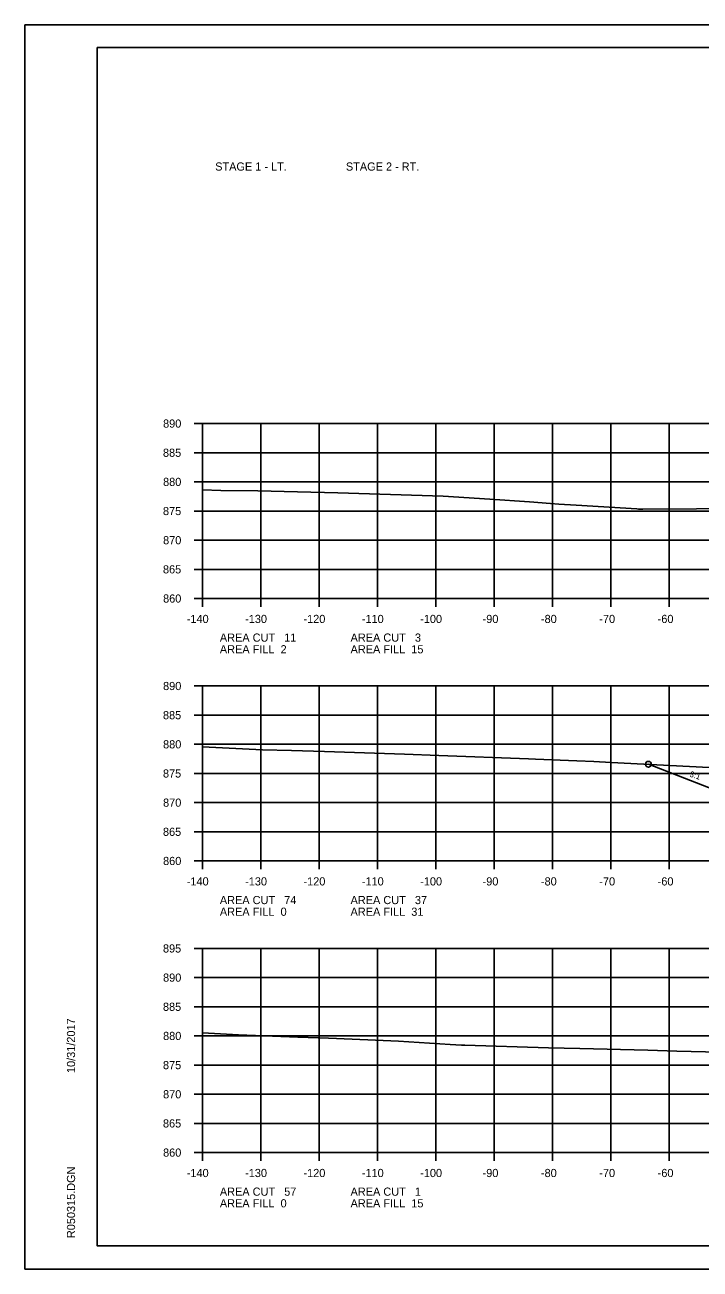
# Model space of a CAD drawing. Extents: x 1486524 to 1499135, y 326561 to 337924.
# Drawn here: x 1488812.5 to 1488928.2, y 332566 to 332779.3 of the extents above; entities that cross this region are included whole.
import ezdxf

# ---------------------------------------------------------------- set-up
doc = ezdxf.new("R2010")
doc.units = 0
for name, color, linetype in [('Default', 7, 'Continuous'), ('E_Const Align', 7, 'Continuous'), ('E_Const Align Station', 7, 'Continuous'), ('E_Ownership Information', 7, 'Continuous'), ('E_Property Line', 7, 'Continuous'), ('E_Quarter Calls', 7, 'Continuous'), ('E_Title Sheet', 7, 'Continuous'), ('E_Tract Number', 7, 'Continuous'), ('R_Xsect Slope', 7, 'Continuous')]:
    doc.layers.add(name, color=color, linetype=linetype)

msp = doc.modelspace()

# ---------------------------------------------------------------- linework, layer by layer
at = {"layer": 'E_Const Align'}
for p, q in [((1488841.49, 332710.95), (1488842.89, 332710.95)), ((1488842.89, 332680.95), (1488842.89, 332710.95)), ((1488841.49, 332705.95), (1488842.89, 332705.95)), ((1488841.49, 332700.95), (1488842.89, 332700.95)), ((1488841.49, 332695.95), (1488842.89, 332695.95)), ((1488841.49, 332690.95), (1488842.89, 332690.95)), ((1488841.49, 332685.95), (1488842.89, 332685.95)), ((1488841.49, 332680.95), (1488842.89, 332680.95)), ((1488842.89, 332679.55), (1488842.89, 332680.95)), ((1488852.89, 332679.55), (1488852.89, 332680.95)), ((1488862.89, 332679.55), (1488862.89, 332680.95)), ((1488872.89, 332679.55), (1488872.89, 332680.95)), ((1488882.89, 332679.55), (1488882.89, 332680.95)), ((1488892.89, 332679.55), (1488892.89, 332680.95)), ((1488902.89, 332679.55), (1488902.89, 332680.95)), ((1488912.89, 332679.55), (1488912.89, 332680.95)), ((1488922.89, 332679.55), (1488922.89, 332680.95)), ((1488841.49, 332665.95), (1488842.89, 332665.95)), ((1488842.89, 332635.95), (1488842.89, 332665.95)), ((1488841.49, 332660.95), (1488842.89, 332660.95)), ((1488841.49, 332655.95), (1488842.89, 332655.95)), ((1488841.49, 332650.95), (1488842.89, 332650.95)), ((1488841.49, 332645.95), (1488842.89, 332645.95)), ((1488841.49, 332640.95), (1488842.89, 332640.95)), ((1488841.49, 332635.95), (1488842.89, 332635.95)), ((1488842.89, 332635.95), (1489122.89, 332635.95)), ((1488842.89, 332634.55), (1488842.89, 332635.95)), ((1488852.89, 332634.55), (1488852.89, 332635.95)), ((1488862.89, 332634.55), (1488862.89, 332635.95)), ((1488872.89, 332634.55), (1488872.89, 332635.95)), ((1488882.89, 332634.55), (1488882.89, 332635.95)), ((1488892.89, 332634.55), (1488892.89, 332635.95)), ((1488902.89, 332634.55), (1488902.89, 332635.95)), ((1488912.89, 332634.55), (1488912.89, 332635.95)), ((1488922.89, 332634.55), (1488922.89, 332635.95)), ((1488841.49, 332620.95), (1488842.89, 332620.95)), ((1488842.89, 332585.95), (1488842.89, 332620.95)), ((1488841.49, 332615.95), (1488842.89, 332615.95)), ((1488841.49, 332610.95), (1488842.89, 332610.95)), ((1488841.49, 332605.95), (1488842.89, 332605.95)), ((1488841.49, 332600.95), (1488842.89, 332600.95)), ((1488841.49, 332595.95), (1488842.89, 332595.95)), ((1488841.49, 332590.95), (1488842.89, 332590.95)), ((1488841.49, 332585.95), (1488842.89, 332585.95)), ((1488842.89, 332585.95), (1489122.89, 332585.95)), ((1488842.89, 332584.55), (1488842.89, 332585.95)), ((1488852.89, 332584.55), (1488852.89, 332585.95)), ((1488862.89, 332584.55), (1488862.89, 332585.95)), ((1488872.89, 332584.55), (1488872.89, 332585.95)), ((1488882.89, 332584.55), (1488882.89, 332585.95)), ((1488892.89, 332584.55), (1488892.89, 332585.95)), ((1488902.89, 332584.55), (1488902.89, 332585.95)), ((1488912.89, 332584.55), (1488912.89, 332585.95)), ((1488922.89, 332584.55), (1488922.89, 332585.95))]:
    msp.add_line(p, q, dxfattribs=at)
at = {"layer": 'E_Ownership Information'}
for p, q in [((1488842.89, 332710.95), (1489122.89, 332710.95)), ((1488842.89, 332680.95), (1488842.89, 332710.95)), ((1488852.89, 332680.95), (1488852.89, 332710.95)), ((1488862.89, 332680.95), (1488862.89, 332710.95)), ((1488872.89, 332680.95), (1488872.89, 332710.95)), ((1488882.89, 332680.95), (1488882.89, 332710.95)), ((1488892.89, 332680.95), (1488892.89, 332710.95)), ((1488902.89, 332680.95), (1488902.89, 332710.95)), ((1488912.89, 332680.95), (1488912.89, 332710.95)), ((1488922.89, 332680.95), (1488922.89, 332710.95)), ((1488842.89, 332705.95), (1489122.89, 332705.95)), ((1488842.89, 332700.95), (1489122.89, 332700.95)), ((1488842.89, 332695.95), (1489122.89, 332695.95)), ((1488842.89, 332690.95), (1489122.89, 332690.95)), ((1488842.89, 332685.95), (1489122.89, 332685.95)), ((1488842.89, 332680.95), (1489122.89, 332680.95)), ((1488842.89, 332665.95), (1489122.89, 332665.95)), ((1488842.89, 332635.95), (1488842.89, 332665.95)), ((1488852.89, 332635.95), (1488852.89, 332665.95)), ((1488862.89, 332635.95), (1488862.89, 332665.95)), ((1488872.89, 332635.95), (1488872.89, 332665.95)), ((1488882.89, 332635.95), (1488882.89, 332665.95)), ((1488892.89, 332635.95), (1488892.89, 332665.95)), ((1488902.89, 332635.95), (1488902.89, 332665.95)), ((1488912.89, 332635.95), (1488912.89, 332665.95)), ((1488922.89, 332635.95), (1488922.89, 332665.95)), ((1488842.89, 332660.95), (1489122.89, 332660.95)), ((1488842.89, 332655.95), (1489122.89, 332655.95)), ((1488842.89, 332650.95), (1489122.89, 332650.95)), ((1488842.89, 332645.95), (1489122.89, 332645.95)), ((1488842.89, 332640.95), (1489122.89, 332640.95)), ((1488842.89, 332635.95), (1489122.89, 332635.95)), ((1488842.89, 332620.95), (1489122.89, 332620.95)), ((1488842.89, 332585.95), (1488842.89, 332620.95)), ((1488852.89, 332585.95), (1488852.89, 332620.95)), ((1488862.89, 332585.95), (1488862.89, 332620.95)), ((1488872.89, 332585.95), (1488872.89, 332620.95)), ((1488882.89, 332585.95), (1488882.89, 332620.95)), ((1488892.89, 332585.95), (1488892.89, 332620.95)), ((1488902.89, 332585.95), (1488902.89, 332620.95)), ((1488912.89, 332585.95), (1488912.89, 332620.95)), ((1488922.89, 332585.95), (1488922.89, 332620.95)), ((1488842.89, 332615.95), (1489122.89, 332615.95)), ((1488842.89, 332610.95), (1489122.89, 332610.95)), ((1488842.89, 332605.95), (1489122.89, 332605.95)), ((1488842.89, 332600.95), (1489122.89, 332600.95)), ((1488842.89, 332595.95), (1489122.89, 332595.95)), ((1488842.89, 332590.95), (1489122.89, 332590.95)), ((1488842.89, 332585.95), (1489122.89, 332585.95))]:
    msp.add_line(p, q, dxfattribs=at)
at = {"layer": 'E_Property Line'}
for p, q in [((1488824.89, 332775.41), (1489141.07, 332775.41)), ((1488824.89, 332569.95), (1488824.89, 332775.41)), ((1488824.89, 332569.95), (1488824.89, 332569.95)), ((1489141.07, 332569.95), (1488824.89, 332569.95))]:
    msp.add_line(p, q, dxfattribs=at)
at = {"layer": 'E_Quarter Calls'}
for p, q in [((1488812.48, 332779.31), (1489145.82, 332779.31)), ((1488812.48, 332565.97), (1489145.82, 332565.97))]:
    msp.add_line(p, q, dxfattribs=at)
for points in [[(1488812.48, 332779.31), (1489145.82, 332779.31), (1489145.82, 332565.97), (1488812.48, 332565.97)], [(1489058.81, 332775.41), (1489058.81, 332765.53), (1489094.54, 332765.53), (1489094.54, 332762.61), (1489117.74, 332762.61), (1489117.74, 332738.28), (1489141.07, 332738.28), (1489141.07, 332569.95), (1488824.89, 332569.95), (1488824.89, 332775.41)]]:
    msp.add_lwpolyline(points, close=True, dxfattribs=at)
msp.add_circle((1488919.33, 332652.53), 0.5, dxfattribs=at)
at = {"layer": 'E_Title Sheet'}
msp.add_lwpolyline([(1488919.35, 332652.54), (1488932.7, 332647.34)], dxfattribs=at)
at = {"layer": 'E_Tract Number'}
for points in [[(1488842.89, 332699.6), (1488846.08, 332699.48), (1488852.38, 332699.4), (1488859.18, 332699.26), (1488866.11, 332699.06), (1488884.17, 332698.5), (1488892.15, 332697.99), (1488898.96, 332697.54), (1488902.57, 332697.27), (1488903.99, 332697.14), (1488906.97, 332696.94), (1488917.37, 332696.3), (1488917.66, 332696.29), (1488918.4, 332696.29), (1488927.59, 332696.33), (1488942.24, 332696.39)], [(1488842.89, 332655.5), (1488853.22, 332655), (1488858.14, 332654.88), (1488863.81, 332654.7), (1488877.51, 332654.28), (1488883.39, 332654.05), (1488898.81, 332653.47), (1488899.97, 332653.41), (1488907.04, 332653.13), (1488910, 332653.01), (1488912.95, 332652.86), (1488931.96, 332651.88)], [(1488842.89, 332606.5), (1488849.09, 332606.11), (1488859.24, 332605.72), (1488864.52, 332605.55), (1488871.24, 332605.27), (1488876.51, 332605.04), (1488885.37, 332604.49), (1488887.28, 332604.39), (1488887.87, 332604.36), (1488902.2, 332603.92), (1488907.61, 332603.78), (1488919.21, 332603.5), (1488924.23, 332603.35), (1488939.02, 332602.99)]]:
    msp.add_lwpolyline(points, dxfattribs=at)

# ---------------------------------------------------------------- texts
at = {"layer": 'Default'}
for s, p in [('STAGE 1 - LT.', (1488845.09, 332754.32)), ('STAGE 2 - RT.', (1488867.49, 332754.32))]:
    msp.add_text(s, height=1.4, dxfattribs=at).set_placement(p)
at = {"layer": 'E_Const Align Station'}
for s, p in [('890', (1488836.16, 332710.25)), ('885', (1488836.14, 332705.25)), ('880', (1488836.16, 332700.25)), ('875', (1488836.14, 332695.25)), ('870', (1488836.16, 332690.25)), ('865', (1488836.14, 332685.25)), ('860', (1488836.16, 332680.25)), ('-140', (1488840.22, 332676.75)), ('-130', (1488850.22, 332676.75)), ('-120', (1488860.22, 332676.75)), ('-110', (1488870.22, 332676.75)), ('-100', (1488880.22, 332676.75)), ('-90', (1488890.92, 332676.75)), ('-80', (1488900.92, 332676.75)), ('-70', (1488910.92, 332676.75)), ('-60', (1488920.92, 332676.75)), ('AREA CUT   11', (1488845.89, 332673.55)), ('AREA CUT   3', (1488868.29, 332673.55)), ('AREA FILL  2', (1488845.89, 332671.55)), ('AREA FILL  15', (1488868.29, 332671.55)), ('890', (1488836.16, 332665.25)), ('885', (1488836.14, 332660.25)), ('880', (1488836.16, 332655.25)), ('875', (1488836.14, 332650.25)), ('870', (1488836.16, 332645.25)), ('865', (1488836.14, 332640.25)), ('860', (1488836.16, 332635.25)), ('-140', (1488840.22, 332631.75)), ('-130', (1488850.22, 332631.75)), ('-120', (1488860.22, 332631.75)), ('-110', (1488870.22, 332631.75)), ('-100', (1488880.22, 332631.75)), ('-90', (1488890.92, 332631.75)), ('-80', (1488900.92, 332631.75)), ('-70', (1488910.92, 332631.75)), ('-60', (1488920.92, 332631.75)), ('AREA CUT   74', (1488845.89, 332628.55)), ('AREA CUT   37', (1488868.29, 332628.55)), ('AREA FILL  0', (1488845.89, 332626.55)), ('AREA FILL  31', (1488868.29, 332626.55)), ('895', (1488836.14, 332620.25)), ('890', (1488836.16, 332615.25)), ('885', (1488836.14, 332610.25)), ('880', (1488836.16, 332605.25)), ('875', (1488836.14, 332600.25)), ('870', (1488836.16, 332595.25)), ('865', (1488836.14, 332590.25)), ('860', (1488836.16, 332585.25)), ('-140', (1488840.22, 332581.75)), ('-130', (1488850.22, 332581.75)), ('-120', (1488860.22, 332581.75)), ('-110', (1488870.22, 332581.75)), ('-100', (1488880.22, 332581.75)), ('-90', (1488890.92, 332581.75)), ('-80', (1488900.92, 332581.75)), ('-70', (1488910.92, 332581.75)), ('-60', (1488920.92, 332581.75)), ('AREA CUT   57', (1488845.89, 332578.55)), ('AREA CUT   1', (1488868.29, 332578.55)), ('AREA FILL  0', (1488845.89, 332576.55)), ('AREA FILL  15', (1488868.29, 332576.55))]:
    msp.add_text(s, height=1.4, dxfattribs=at).set_placement(p)
at = {"layer": 'E_Property Line'}
for s, p in [('10/31/2017', (1488821.08, 332599.59)), ('R050315.DGN', (1488821.08, 332571.28))]:
    msp.add_text(s, height=1.4, rotation=90, dxfattribs=at).set_placement(p)
at = {"layer": 'R_Xsect Slope'}
msp.add_text('3:1', height=1, rotation=341.5651, dxfattribs=at).set_placement((1488926.31, 332650.44))

doc.saveas('drawing.dxf')
